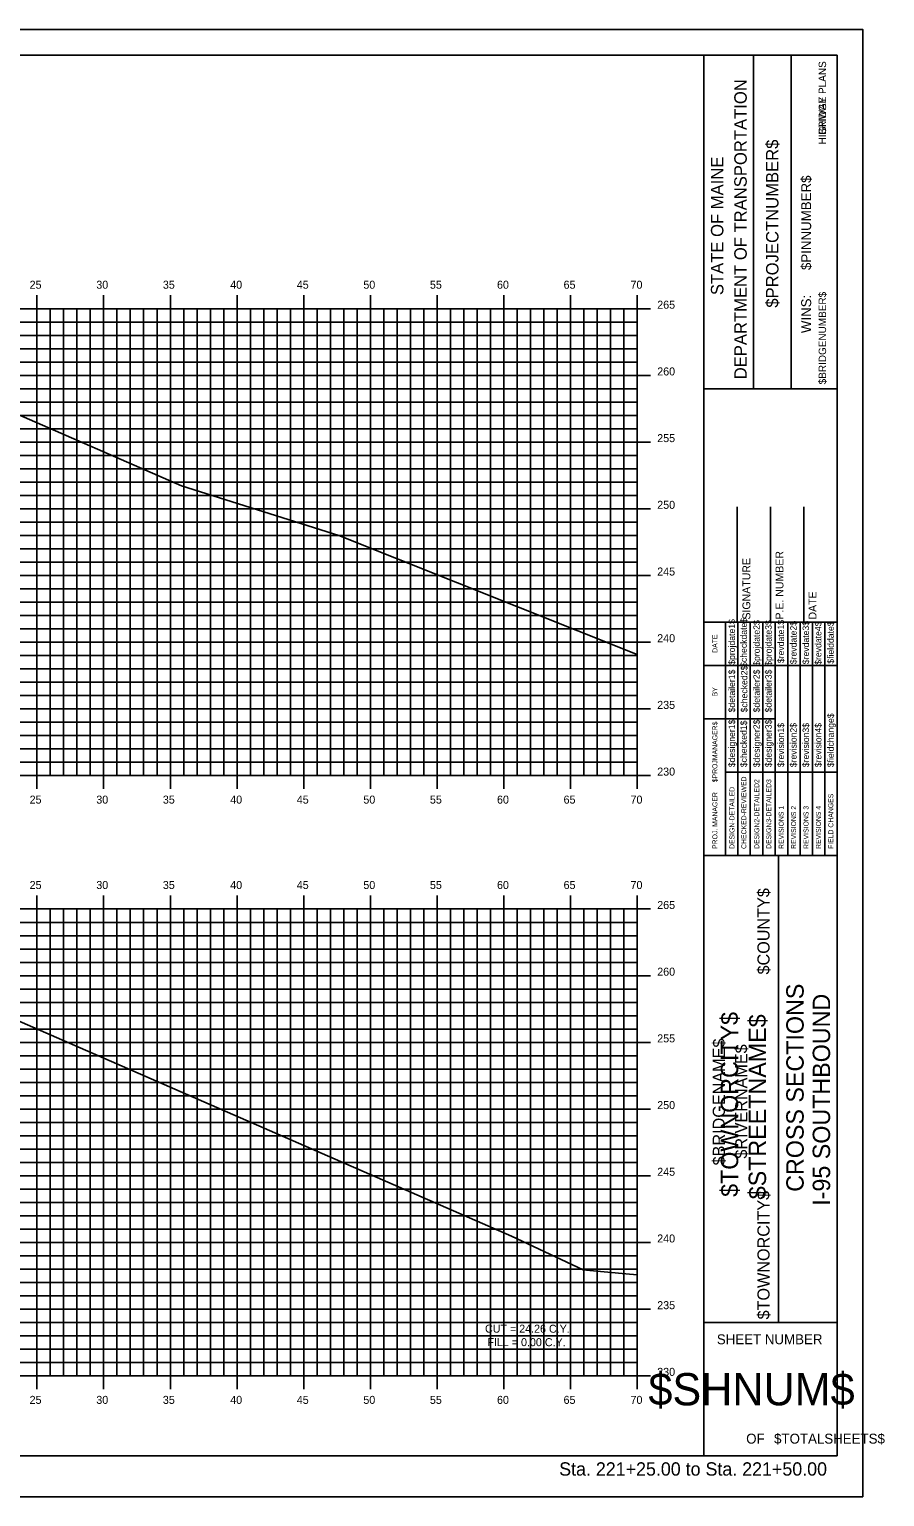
# Model space of a CAD drawing. Extents: x -22 to 1480, y -1511 to 8.
# Drawn here: x 1194.1 to 1258.3, y -184.5 to -74.5 of the extents above; entities that cross this region are included whole.
import ezdxf

# ---------------------------------------------------------------- set-up
doc = ezdxf.new("R2010")
doc.units = 0
for name, color, linetype in [('ANNOTATION', 7, 'Continuous'), ('BORDER', 7, 'Continuous'), ('BRIDGE_TITLE', 7, 'Continuous'), ('H_V ANNOTATION', 7, 'Continuous'), ('HIGHWAY_TITLE', 7, 'Continuous'), ('MAJOR', 7, 'Continuous'), ('MINOR', 7, 'Continuous'), ('PLOT BOUNDARY', 7, 'Continuous'), ('S_Roadway_Centerline', 7, 'Continuous')]:
    doc.layers.add(name, color=color, linetype=linetype)

msp = doc.modelspace()

# ---------------------------------------------------------------- linework, layer by layer
at = {"layer": 'BORDER'}
for p, q in [((1254.72, -76.47), (1094.72, -76.47)), ((1244.72, -181.46), (1244.72, -76.46)), ((1248.45, -101.47), (1248.45, -76.47)), ((1251.25, -101.47), (1251.25, -76.47)), ((1254.72, -181.46), (1254.72, -76.46)), ((1244.72, -101.47), (1254.72, -101.47)), ((1247.22, -118.96), (1247.22, -110.32)), ((1249.72, -118.96), (1249.72, -110.32)), ((1252.22, -118.96), (1252.22, -110.32)), ((1244.72, -118.96), (1254.72, -118.96)), ((1244.72, -136.46), (1254.72, -136.46)), ((1250.31, -171.46), (1250.31, -136.46)), ((1244.72, -171.46), (1254.72, -171.46)), ((1094.72, -181.47), (1254.72, -181.47))]:
    msp.add_line(p, q, dxfattribs=at)
for points in [[(1246.34, -122.21), (1246.34, -118.96)], [(1246.34, -136.46), (1246.34, -119.67)], [(1247.27, -136.46), (1247.27, -118.96)], [(1248.2, -118.96), (1248.2, -136.46)], [(1249.13, -136.46), (1249.13, -118.96)], [(1250.06, -136.46), (1250.06, -118.96)], [(1251, -136.46), (1251, -118.96)], [(1251.93, -136.46), (1251.93, -118.96)], [(1252.86, -136.46), (1252.86, -118.96)], [(1253.79, -136.46), (1253.79, -118.96)], [(1244.72, -122.21), (1254.72, -122.21)], [(1244.72, -126.21), (1246.34, -126.21)], [(1246.34, -126.21), (1250.06, -126.21)], [(1246.34, -130.21), (1254.72, -130.21)]]:
    msp.add_lwpolyline(points, dxfattribs=at)
at = {"layer": 'MAJOR'}
for p, q in [((1194.72, -94.46), (1194.72, -95.47)), ((1199.72, -94.46), (1199.72, -95.47)), ((1204.72, -94.46), (1204.72, -95.47)), ((1209.72, -94.46), (1209.72, -95.47)), ((1214.72, -94.46), (1214.72, -95.47)), ((1219.72, -94.46), (1219.72, -95.47)), ((1224.72, -94.46), (1224.72, -95.47)), ((1229.72, -94.46), (1229.72, -95.47)), ((1234.72, -94.46), (1234.72, -95.47)), ((1239.72, -94.46), (1239.72, -95.47)), ((1099.72, -95.47), (1239.72, -95.47)), ((1099.72, -95.47), (1239.72, -95.47)), ((1194.72, -130.47), (1194.72, -95.47)), ((1199.72, -130.47), (1199.72, -95.47)), ((1204.72, -130.47), (1204.72, -95.47)), ((1209.72, -130.47), (1209.72, -95.47)), ((1214.72, -130.47), (1214.72, -95.47)), ((1219.72, -130.47), (1219.72, -95.47)), ((1224.72, -130.47), (1224.72, -95.47)), ((1229.72, -130.47), (1229.72, -95.47)), ((1234.72, -130.47), (1234.72, -95.47)), ((1240.72, -95.47), (1238.72, -95.47)), ((1239.72, -130.47), (1239.72, -95.47)), ((1239.72, -130.47), (1239.72, -95.47)), ((1099.72, -100.47), (1239.72, -100.47)), ((1240.72, -100.47), (1238.72, -100.47)), ((1099.72, -105.47), (1239.72, -105.47)), ((1240.72, -105.47), (1238.72, -105.47)), ((1099.72, -110.47), (1239.72, -110.47)), ((1240.72, -110.47), (1238.72, -110.47)), ((1099.72, -115.47), (1239.72, -115.47)), ((1240.72, -115.47), (1238.72, -115.47)), ((1099.72, -120.47), (1239.72, -120.47)), ((1240.72, -120.47), (1238.72, -120.47)), ((1099.72, -125.47), (1239.72, -125.47)), ((1240.72, -125.47), (1238.72, -125.47)), ((1099.72, -130.47), (1239.72, -130.47)), ((1099.72, -130.47), (1239.72, -130.47)), ((1194.72, -131.47), (1194.72, -130.47)), ((1199.72, -131.47), (1199.72, -130.47)), ((1204.72, -131.47), (1204.72, -130.47)), ((1209.72, -131.47), (1209.72, -130.47)), ((1214.72, -131.47), (1214.72, -130.47)), ((1219.72, -131.47), (1219.72, -130.47)), ((1224.72, -131.47), (1224.72, -130.47)), ((1229.72, -131.47), (1229.72, -130.47)), ((1234.72, -131.47), (1234.72, -130.47)), ((1240.72, -130.47), (1238.72, -130.47)), ((1239.72, -131.47), (1239.72, -130.47)), ((1194.72, -139.46), (1194.72, -140.47)), ((1199.72, -139.46), (1199.72, -140.47)), ((1204.72, -139.46), (1204.72, -140.47)), ((1209.72, -139.46), (1209.72, -140.47)), ((1214.72, -139.46), (1214.72, -140.47)), ((1219.72, -139.46), (1219.72, -140.47)), ((1224.72, -139.46), (1224.72, -140.47)), ((1229.72, -139.46), (1229.72, -140.47)), ((1234.72, -139.46), (1234.72, -140.47)), ((1239.72, -139.46), (1239.72, -140.47)), ((1099.72, -140.47), (1239.72, -140.47)), ((1099.72, -140.47), (1239.72, -140.47)), ((1194.72, -175.47), (1194.72, -140.47)), ((1199.72, -175.47), (1199.72, -140.47)), ((1204.72, -175.47), (1204.72, -140.47)), ((1209.72, -175.47), (1209.72, -140.47)), ((1214.72, -175.47), (1214.72, -140.47)), ((1219.72, -175.47), (1219.72, -140.47)), ((1224.72, -175.47), (1224.72, -140.47)), ((1229.72, -175.47), (1229.72, -140.47)), ((1234.72, -175.47), (1234.72, -140.47)), ((1240.72, -140.47), (1238.72, -140.47)), ((1239.72, -175.47), (1239.72, -140.47)), ((1239.72, -175.47), (1239.72, -140.47)), ((1099.72, -145.47), (1239.72, -145.47)), ((1240.72, -145.47), (1238.72, -145.47)), ((1099.72, -150.47), (1239.72, -150.47)), ((1240.72, -150.47), (1238.72, -150.47)), ((1099.72, -155.47), (1239.72, -155.47)), ((1240.72, -155.47), (1238.72, -155.47)), ((1099.72, -160.47), (1239.72, -160.47)), ((1240.72, -160.47), (1238.72, -160.47)), ((1099.72, -165.47), (1239.72, -165.47)), ((1240.72, -165.47), (1238.72, -165.47)), ((1099.72, -170.47), (1239.72, -170.47)), ((1240.72, -170.47), (1238.72, -170.47)), ((1099.72, -175.47), (1239.72, -175.47)), ((1099.72, -175.47), (1239.72, -175.47)), ((1194.72, -176.47), (1194.72, -175.47)), ((1199.72, -176.47), (1199.72, -175.47)), ((1204.72, -176.47), (1204.72, -175.47)), ((1209.72, -176.47), (1209.72, -175.47)), ((1214.72, -176.47), (1214.72, -175.47)), ((1219.72, -176.47), (1219.72, -175.47)), ((1224.72, -176.47), (1224.72, -175.47)), ((1229.72, -176.47), (1229.72, -175.47)), ((1234.72, -176.47), (1234.72, -175.47)), ((1240.72, -175.47), (1238.72, -175.47)), ((1239.72, -176.47), (1239.72, -175.47))]:
    msp.add_line(p, q, dxfattribs=at)
at = {"layer": 'MINOR'}
for p, q in [((1195.72, -130.47), (1195.72, -95.47)), ((1196.72, -130.47), (1196.72, -95.47)), ((1197.72, -130.47), (1197.72, -95.47)), ((1198.72, -130.47), (1198.72, -95.47)), ((1200.72, -130.47), (1200.72, -95.47)), ((1201.72, -130.47), (1201.72, -95.47)), ((1202.72, -130.47), (1202.72, -95.47)), ((1203.72, -130.47), (1203.72, -95.47)), ((1205.72, -130.47), (1205.72, -95.47)), ((1206.72, -130.47), (1206.72, -95.47)), ((1207.72, -130.47), (1207.72, -95.47)), ((1208.72, -130.47), (1208.72, -95.47)), ((1210.72, -130.47), (1210.72, -95.47)), ((1211.72, -130.47), (1211.72, -95.47)), ((1212.72, -130.47), (1212.72, -95.47)), ((1213.72, -130.47), (1213.72, -95.47)), ((1215.72, -130.47), (1215.72, -95.47)), ((1216.72, -130.47), (1216.72, -95.47)), ((1217.72, -130.47), (1217.72, -95.47)), ((1218.72, -130.47), (1218.72, -95.47)), ((1220.72, -130.47), (1220.72, -95.47)), ((1221.72, -130.47), (1221.72, -95.47)), ((1222.72, -130.47), (1222.72, -95.47)), ((1223.72, -130.47), (1223.72, -95.47)), ((1225.72, -130.47), (1225.72, -95.47)), ((1226.72, -130.47), (1226.72, -95.47)), ((1227.72, -130.47), (1227.72, -95.47)), ((1228.72, -130.47), (1228.72, -95.47)), ((1230.72, -130.47), (1230.72, -95.47)), ((1231.72, -130.47), (1231.72, -95.47)), ((1232.72, -130.47), (1232.72, -95.47)), ((1233.72, -130.47), (1233.72, -95.47)), ((1235.72, -130.47), (1235.72, -95.47)), ((1236.72, -130.47), (1236.72, -95.47)), ((1237.72, -130.47), (1237.72, -95.47)), ((1238.72, -130.47), (1238.72, -95.47)), ((1099.72, -96.47), (1239.72, -96.47)), ((1239.72, -96.47), (1238.72, -96.47)), ((1099.72, -97.47), (1239.72, -97.47)), ((1239.72, -97.47), (1238.72, -97.47)), ((1099.72, -98.47), (1239.72, -98.47)), ((1239.72, -98.47), (1238.72, -98.47)), ((1099.72, -99.47), (1239.72, -99.47)), ((1239.72, -99.47), (1238.72, -99.47)), ((1099.72, -101.47), (1239.72, -101.47)), ((1239.72, -101.47), (1238.72, -101.47)), ((1099.72, -102.47), (1239.72, -102.47)), ((1239.72, -102.47), (1238.72, -102.47)), ((1099.72, -103.47), (1239.72, -103.47)), ((1099.72, -104.47), (1239.72, -104.47)), ((1239.72, -103.47), (1238.72, -103.47)), ((1239.72, -104.47), (1238.72, -104.47)), ((1099.72, -106.47), (1239.72, -106.47)), ((1239.72, -106.47), (1238.72, -106.47)), ((1099.72, -107.47), (1239.72, -107.47)), ((1239.72, -107.47), (1238.72, -107.47)), ((1099.72, -108.47), (1239.72, -108.47)), ((1239.72, -108.47), (1238.72, -108.47)), ((1099.72, -109.47), (1239.72, -109.47)), ((1239.72, -109.47), (1238.72, -109.47)), ((1099.72, -111.47), (1239.72, -111.47)), ((1239.72, -111.47), (1238.72, -111.47)), ((1099.72, -112.47), (1239.72, -112.47)), ((1239.72, -112.47), (1238.72, -112.47)), ((1099.72, -113.47), (1239.72, -113.47)), ((1239.72, -113.47), (1238.72, -113.47)), ((1099.72, -114.47), (1239.72, -114.47)), ((1239.72, -114.47), (1238.72, -114.47)), ((1099.72, -116.47), (1239.72, -116.47)), ((1239.72, -116.47), (1238.72, -116.47)), ((1099.72, -117.47), (1239.72, -117.47)), ((1239.72, -117.47), (1238.72, -117.47)), ((1099.72, -118.47), (1239.72, -118.47)), ((1239.72, -118.47), (1238.72, -118.47)), ((1099.72, -119.47), (1239.72, -119.47)), ((1239.72, -119.47), (1238.72, -119.47)), ((1099.72, -121.47), (1239.72, -121.47)), ((1239.72, -121.47), (1238.72, -121.47)), ((1099.72, -122.47), (1239.72, -122.47)), ((1239.72, -122.47), (1238.72, -122.47)), ((1099.72, -123.47), (1239.72, -123.47)), ((1239.72, -123.47), (1238.72, -123.47)), ((1099.72, -124.47), (1239.72, -124.47)), ((1239.72, -124.47), (1238.72, -124.47)), ((1099.72, -126.47), (1239.72, -126.47)), ((1239.72, -126.47), (1238.72, -126.47)), ((1099.72, -127.47), (1239.72, -127.47)), ((1239.72, -127.47), (1238.72, -127.47)), ((1099.72, -128.47), (1239.72, -128.47)), ((1239.72, -128.47), (1238.72, -128.47)), ((1099.72, -129.47), (1239.72, -129.47)), ((1239.72, -129.47), (1238.72, -129.47)), ((1195.72, -175.47), (1195.72, -140.47)), ((1196.72, -175.47), (1196.72, -140.47)), ((1197.72, -175.47), (1197.72, -140.47)), ((1198.72, -175.47), (1198.72, -140.47)), ((1200.72, -175.47), (1200.72, -140.47)), ((1201.72, -175.47), (1201.72, -140.47)), ((1202.72, -175.47), (1202.72, -140.47)), ((1203.72, -175.47), (1203.72, -140.47)), ((1205.72, -175.47), (1205.72, -140.47)), ((1206.72, -175.47), (1206.72, -140.47)), ((1207.72, -175.47), (1207.72, -140.47)), ((1208.72, -175.47), (1208.72, -140.47)), ((1210.72, -175.47), (1210.72, -140.47)), ((1211.72, -175.47), (1211.72, -140.47)), ((1212.72, -175.47), (1212.72, -140.47)), ((1213.72, -175.47), (1213.72, -140.47)), ((1215.72, -175.47), (1215.72, -140.47)), ((1216.72, -175.47), (1216.72, -140.47)), ((1217.72, -175.47), (1217.72, -140.47)), ((1218.72, -175.47), (1218.72, -140.47)), ((1220.72, -175.47), (1220.72, -140.47)), ((1221.72, -175.47), (1221.72, -140.47)), ((1222.72, -175.47), (1222.72, -140.47)), ((1223.72, -175.47), (1223.72, -140.47)), ((1225.72, -175.47), (1225.72, -140.47)), ((1226.72, -175.47), (1226.72, -140.47)), ((1227.72, -175.47), (1227.72, -140.47)), ((1228.72, -175.47), (1228.72, -140.47)), ((1230.72, -175.47), (1230.72, -140.47)), ((1231.72, -175.47), (1231.72, -140.47)), ((1232.72, -175.47), (1232.72, -140.47)), ((1233.72, -175.47), (1233.72, -140.47)), ((1235.72, -175.47), (1235.72, -140.47)), ((1236.72, -175.47), (1236.72, -140.47)), ((1237.72, -175.47), (1237.72, -140.47)), ((1238.72, -175.47), (1238.72, -140.47)), ((1099.72, -141.47), (1239.72, -141.47)), ((1239.72, -141.47), (1238.72, -141.47)), ((1099.72, -142.47), (1239.72, -142.47)), ((1239.72, -142.47), (1238.72, -142.47)), ((1099.72, -143.47), (1239.72, -143.47)), ((1239.72, -143.47), (1238.72, -143.47)), ((1099.72, -144.47), (1239.72, -144.47)), ((1239.72, -144.47), (1238.72, -144.47)), ((1099.72, -146.47), (1239.72, -146.47)), ((1239.72, -146.47), (1238.72, -146.47)), ((1099.72, -147.47), (1239.72, -147.47)), ((1099.72, -148.47), (1239.72, -148.47)), ((1239.72, -147.47), (1238.72, -147.47)), ((1239.72, -148.47), (1238.72, -148.47)), ((1099.72, -149.47), (1239.72, -149.47)), ((1239.72, -149.47), (1238.72, -149.47)), ((1099.72, -151.47), (1239.72, -151.47)), ((1239.72, -151.47), (1238.72, -151.47)), ((1099.72, -152.47), (1239.72, -152.47)), ((1239.72, -152.47), (1238.72, -152.47)), ((1099.72, -153.47), (1239.72, -153.47)), ((1239.72, -153.47), (1238.72, -153.47)), ((1099.72, -154.47), (1239.72, -154.47)), ((1239.72, -154.47), (1238.72, -154.47)), ((1099.72, -156.47), (1239.72, -156.47)), ((1239.72, -156.47), (1238.72, -156.47)), ((1099.72, -157.47), (1239.72, -157.47)), ((1239.72, -157.47), (1238.72, -157.47)), ((1099.72, -158.47), (1239.72, -158.47)), ((1099.72, -159.47), (1239.72, -159.47)), ((1239.72, -158.47), (1238.72, -158.47)), ((1239.72, -159.47), (1238.72, -159.47)), ((1099.72, -161.47), (1239.72, -161.47)), ((1239.72, -161.47), (1238.72, -161.47)), ((1099.72, -162.47), (1239.72, -162.47)), ((1239.72, -162.47), (1238.72, -162.47)), ((1099.72, -163.47), (1239.72, -163.47)), ((1239.72, -163.47), (1238.72, -163.47)), ((1099.72, -164.47), (1239.72, -164.47)), ((1239.72, -164.47), (1238.72, -164.47)), ((1099.72, -166.47), (1239.72, -166.47)), ((1239.72, -166.47), (1238.72, -166.47)), ((1099.72, -167.47), (1239.72, -167.47)), ((1239.72, -167.47), (1238.72, -167.47)), ((1099.72, -168.47), (1239.72, -168.47)), ((1239.72, -168.47), (1238.72, -168.47)), ((1099.72, -169.47), (1239.72, -169.47)), ((1239.72, -169.47), (1238.72, -169.47)), ((1099.72, -171.47), (1239.72, -171.47)), ((1239.72, -171.47), (1238.72, -171.47)), ((1099.72, -172.47), (1239.72, -172.47)), ((1239.72, -172.47), (1238.72, -172.47)), ((1099.72, -173.47), (1239.72, -173.47)), ((1239.72, -173.47), (1238.72, -173.47)), ((1099.72, -174.47), (1239.72, -174.47)), ((1239.72, -174.47), (1238.72, -174.47))]:
    msp.add_line(p, q, dxfattribs=at)
at = {"layer": 'PLOT BOUNDARY'}
msp.add_lwpolyline([(1086.63, -184.53), (1256.63, -184.53), (1256.63, -74.53), (1086.63, -74.53)], close=True, dxfattribs=at)
at = {"layer": 'S_Roadway_Centerline'}
for points in [[(1192.38, -102.99), (1205.56, -108.74), (1217.35, -112.48), (1239.72, -121.38)], [(1192.23, -148.39), (1230.29, -164.99), (1235.66, -167.53), (1236.17, -167.57), (1238.87, -167.82), (1239.72, -167.9)]]:
    msp.add_lwpolyline(points, dxfattribs=at)

# ---------------------------------------------------------------- texts
at = {"layer": 'ANNOTATION'}
for s, p in [('CUT = 24.26 C.Y.', (1228.31, -172.23)), ('FILL = 0.00 C.Y.', (1228.49, -173.24))]:
    msp.add_text(s, height=0.6, rotation=359.9241, dxfattribs=at).set_placement(p)
at = {"layer": 'BORDER'}
for s, height, rotation, p in [('DEPARTMENT OF TRANSPORTATION', 0.9318, 90, (1247.93, -100.76)), ('$PROJECTNUMBER$', 0.9318, 90, (1250.31, -95.39)), ('STATE OF MAINE', 0.9318, 90, (1246.18, -94.45)), ('$PINNUMBER$', 0.7453, 90, (1252.76, -92.57)), ('WINS:', 0.745, 90, (1252.76, -97.3)), ('SIGNATURE', 0.591, 90, (1248.2, -118.77)), ('P.E. NUMBER', 0.5906, 90, (1250.68, -118.77)), ('DATE', 0.591, 90, (1253.16, -118.77)), ('$projdate1$', 0.4845, 90, (1247.05, -122.16)), ('$checkdate$', 0.4845, 90, (1247.94, -122.32)), ('$projdate2$', 0.4845, 90, (1248.91, -122.24)), ('$projdate3$', 0.4845, 90, (1249.8, -122.24)), ('$revdate1$', 0.485, 90, (1250.73, -122.04)), ('$revdate2$', 0.485, 90, (1251.67, -122.12)), ('$revdate3$', 0.485, 90, (1252.6, -122.12)), ('$revdate4$', 0.485, 90, (1253.53, -122.16)), ('$fielddate$', 0.4845, 90, (1254.46, -122.08)), ('DATE', 0.371, 90, (1245.73, -121.26)), ('$detailer1$', 0.4845, 90, (1247.05, -125.73)), ('$checked2$', 0.485, 90, (1247.98, -125.73)), ('$detailer2$', 0.4845, 90, (1248.91, -125.73)), ('$detailer3$', 0.4845, 90, (1249.8, -125.73)), ('BY', 0.371, 90, (1245.73, -124.53)), ('$designer1$', 0.4845, 90, (1247.05, -129.84)), ('$checked1$', 0.485, 90, (1247.94, -129.84)), ('$designer2$', 0.4845, 90, (1248.91, -129.84)), ('$designer3$', 0.4845, 90, (1249.8, -129.84)), ('$fieldchange$', 0.4845, 90, (1254.46, -129.84)), ('$PROJMANAGER$', 0.3727, 90, (1245.73, -130.97)), ('$revision1$', 0.4845, 90, (1250.73, -129.84)), ('$revision2$', 0.4845, 90, (1251.67, -129.84)), ('$revision3$', 0.4845, 90, (1252.6, -129.84)), ('$revision4$', 0.4845, 90, (1253.53, -129.84)), ('CHECKED-REVIEWED', 0.3727, 90, (1247.9, -135.97)), ('PROJ. MANAGER', 0.3727, 90, (1245.73, -135.97)), ('DESIGN-DETAILED', 0.3727, 90, (1247.01, -135.97)), ('DESIGN2-DETAILED2', 0.3727, 90, (1248.87, -135.97)), ('DESIGN3-DETAILED3', 0.3727, 90, (1249.77, -135.97)), ('FIELD CHANGES', 0.3727, 90, (1254.42, -135.97)), ('REVISIONS 1', 0.3727, 90, (1250.7, -135.97)), ('REVISIONS 2', 0.3727, 90, (1251.63, -135.97)), ('REVISIONS 3', 0.3727, 90, (1252.56, -135.97)), ('REVISIONS 4', 0.3727, 90, (1253.49, -135.97)), ('CROSS SECTIONS', 1.3043, 90, (1252.2, -161.67)), ('I-95 SOUTHBOUND', 1.3043, 90, (1254.18, -162.72)), ('SHEET NUMBER', 0.7453, 360, (1245.69, -173.1)), ('$SHNUM$', 2.419, 360, (1240.56, -177.68)), ('OF', 0.745, 360, (1247.89, -180.55)), ('$TOTALSHEETS$', 0.7453, 360, (1249.98, -180.55))]:
    msp.add_text(s, height=height, rotation=rotation, dxfattribs=at).set_placement(p)
at = {"layer": 'BRIDGE_TITLE'}
for s, height, p in [('BRIDGE PLANS', 0.559, (1253.88, -82.44)), ('$BRIDGENUMBER$', 0.559, (1253.88, -101.14)), ('$COUNTY$', 0.907, (1249.64, -145.38)), ('$BRIDGENAME$', 0.9072, (1246.29, -159.69)), ('$RIVERNAME$', 0.9072, (1247.97, -159.18)), ('$TOWNORCITY$', 0.9072, (1249.64, -171.24))]:
    msp.add_text(s, height=height, rotation=90, dxfattribs=at).set_placement(p)
at = {"layer": 'H_V ANNOTATION'}
for s, height, p in [('25', 0.6, (1194.17, -93.97)), ('30', 0.6, (1199.17, -93.97)), ('35', 0.6, (1204.16, -93.97)), ('40', 0.6, (1209.21, -93.97)), ('45', 0.6, (1214.2, -93.97)), ('50', 0.6, (1219.19, -93.97)), ('55', 0.6, (1224.18, -93.97)), ('60', 0.6, (1229.21, -93.97)), ('65', 0.6, (1234.2, -93.97)), ('70', 0.6, (1239.22, -93.97)), ('265', 0.6, (1241.22, -95.47)), ('260', 0.6, (1241.22, -100.47)), ('255', 0.6, (1241.22, -105.47)), ('250', 0.6, (1241.22, -110.47)), ('245', 0.6, (1241.22, -115.47)), ('240', 0.6, (1241.22, -120.47)), ('235', 0.6, (1241.22, -125.47)), ('230', 0.6, (1241.22, -130.47)), ('25', 0.6, (1194.17, -132.57)), ('30', 0.6, (1199.17, -132.57)), ('35', 0.6, (1204.16, -132.57)), ('40', 0.6, (1209.21, -132.57)), ('45', 0.6, (1214.2, -132.57)), ('50', 0.6, (1219.19, -132.57)), ('55', 0.6, (1224.18, -132.57)), ('60', 0.6, (1229.21, -132.57)), ('65', 0.6, (1234.2, -132.57)), ('70', 0.6, (1239.22, -132.57)), ('25', 0.6, (1194.17, -138.97)), ('30', 0.6, (1199.17, -138.97)), ('35', 0.6, (1204.16, -138.97)), ('40', 0.6, (1209.21, -138.97)), ('45', 0.6, (1214.2, -138.97)), ('50', 0.6, (1219.19, -138.97)), ('55', 0.6, (1224.18, -138.97)), ('60', 0.6, (1229.21, -138.97)), ('65', 0.6, (1234.2, -138.97)), ('70', 0.6, (1239.22, -138.97)), ('265', 0.6, (1241.22, -140.47)), ('260', 0.6, (1241.22, -145.47)), ('255', 0.6, (1241.22, -150.47)), ('250', 0.6, (1241.22, -155.47)), ('245', 0.6, (1241.22, -160.47)), ('240', 0.6, (1241.22, -165.47)), ('235', 0.6, (1241.22, -170.47)), ('230', 0.6, (1241.22, -175.47)), ('25', 0.6, (1194.17, -177.57)), ('30', 0.6, (1199.17, -177.57)), ('35', 0.6, (1204.16, -177.57)), ('40', 0.6, (1209.21, -177.57)), ('45', 0.6, (1214.2, -177.57)), ('50', 0.6, (1219.19, -177.57)), ('55', 0.6, (1224.18, -177.57)), ('60', 0.6, (1229.21, -177.57)), ('65', 0.6, (1234.2, -177.57)), ('70', 0.6, (1239.22, -177.57)), ('Sta. 221+25.00 to Sta. 221+50.00', 1.0002, (1233.87, -182.95))]:
    msp.add_text(s, height=height, dxfattribs=at).set_placement(p)
at = {"layer": 'HIGHWAY_TITLE'}
for s, height, p in [('HIGHWAY PLANS', 0.559, (1253.88, -83.15)), ('$TOWNORCITY$', 1.3043, (1247.29, -162.05)), ('$STREETNAME$', 1.3043, (1249.38, -162.23))]:
    msp.add_text(s, height=height, rotation=90, dxfattribs=at).set_placement(p)

doc.saveas('drawing.dxf')
